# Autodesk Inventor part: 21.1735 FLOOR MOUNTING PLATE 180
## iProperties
Created: 2007-04
Part Number: 21.1735 FLOOR MOUNTING PLATE 180
Material: Aluminum-6061
Document SubType Name: Modeling
Designer: Andy Moles
Density: 2.71 g/cm^3
Author: Andy Moles
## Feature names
1. Extrusion1
2. Extrusion2
